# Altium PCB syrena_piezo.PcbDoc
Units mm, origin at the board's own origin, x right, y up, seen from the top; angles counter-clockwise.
Board outline 35.94 x 14.99 mm, 2 copper layers (Top Layer, Bottom Layer); 19 components, 15 nets, 54 pads, 10 vias.
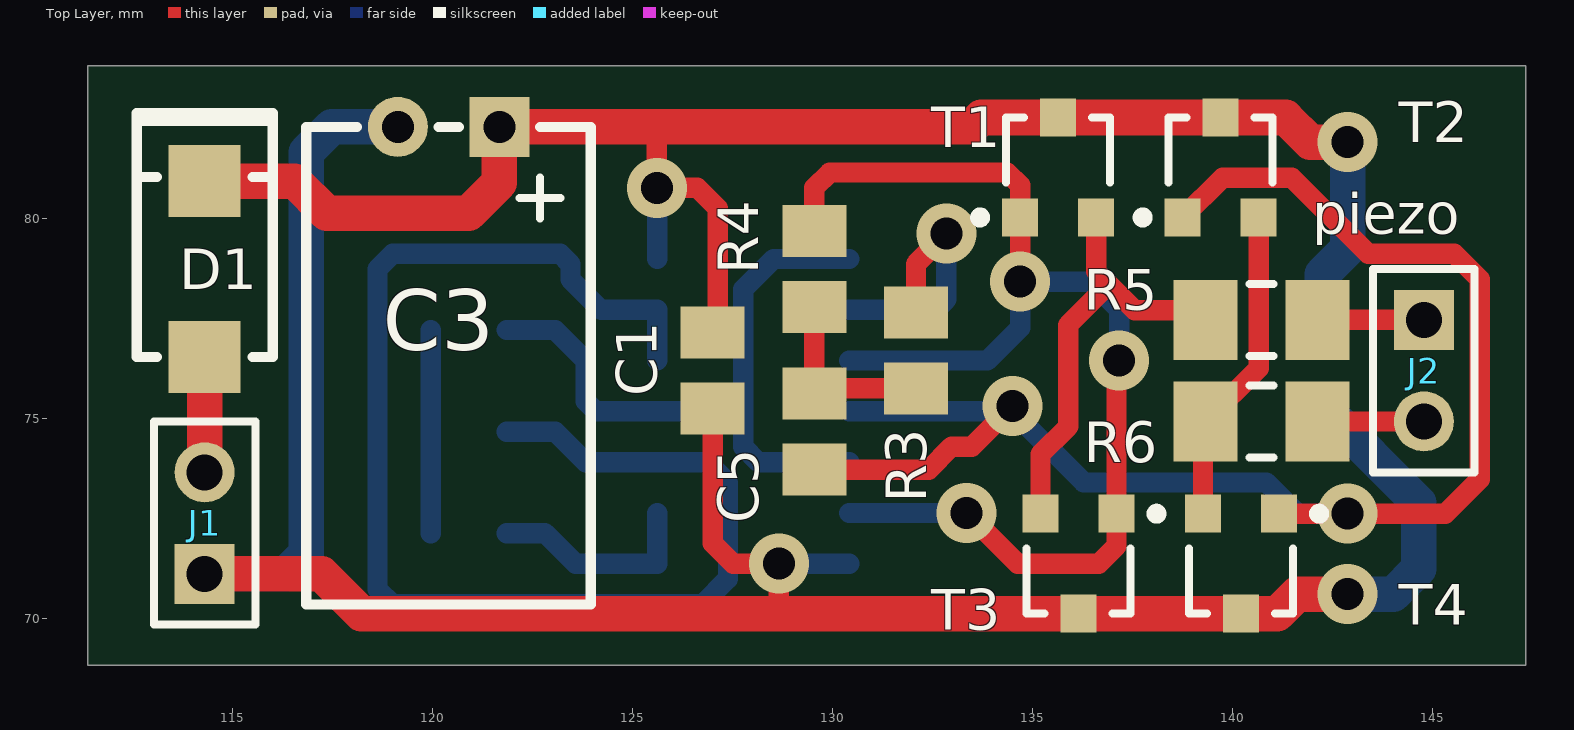
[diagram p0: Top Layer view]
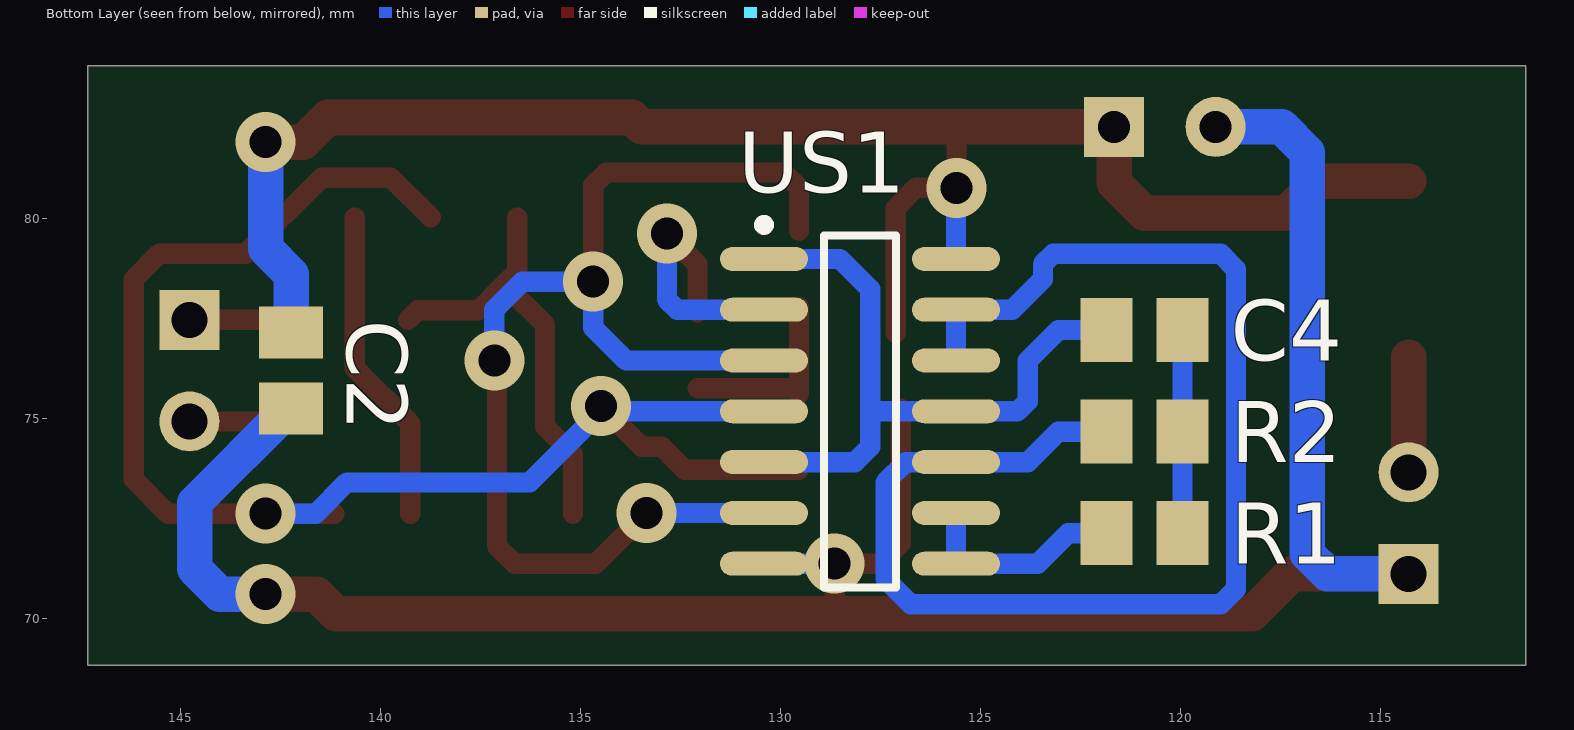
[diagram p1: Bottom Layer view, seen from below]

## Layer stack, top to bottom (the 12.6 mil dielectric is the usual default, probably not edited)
Top Layer: signal copper 0.0356
Dielectric: dielectric 0.32, FR-4, Dk 4.8
Bottom Layer: signal copper 0.0356

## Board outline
111.379,68.834 147.32,68.834 147.32,83.82 111.379,83.82

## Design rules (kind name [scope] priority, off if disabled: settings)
Clearance [All] p1: gap=0.254
PolygonConnect [All] p1: connectstyle=Relief reliefconductorwidth=0.254 reliefentries=4 polygonreliefangle="90 Angle"
RoomDefinition syrena_piezo [InComponentClass('syrena_piezo')] p1: confinementstyle=ConfineIn formatcopy=TRUE lockcomponents=FALSE outline 0,0 50.8,0 50.8,25.4 0,25.4
RoutingVias [All] p1: holewidth=0.711 width=1.27 viastyle="Through Hole" minholewidth=0.711 minwidth=1.27 maxholewidth=0.711 maxwidth=1.27
SilkscreenOverComponentPads [All] p1: minsilkscreentomaskgap=0.254
SolderMaskExpansion [All] p1: expansion=0.102
Width [All] p1: maxlimit=2.54 minlimit=0.254 preferedwidth=0.508
27 further rules are at their usual default settings.

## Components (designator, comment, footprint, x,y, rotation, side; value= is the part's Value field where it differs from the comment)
C1 "100n" MELF-0805 127,76.2 r90 top
C2 "1u" MELF-0805 142.24,76.2 r90 bottom
C3 "100u" "2,5/7mm le抗cy elektrolit" 120.396,82.296 r180 top
C4 "1u" MELF-0805 120.904,77.216 r0 bottom
C5 "100n" MELF-0805 129.54,74.676 r270 top
D1 "SS14" SMA/DO-214AC 114.3,78.74 r90 top
J1 "zasilanie" HDR1X2 114.3,71.12 r90 top
J2 "piezo" HDR1X2 144.78,77.47 r270 top
R1 "100k" MELF-0805 120.904,72.136 r0 bottom
R2 "180k" MELF-0805 120.904,74.676 r0 bottom
R3 "100k" MELF-0805 132.08,76.708 r90 top
R4 "1,8k" MELF-0805 129.54,78.74 r90 top
R5 "4,7" MELF-1206 140.716,77.47 r0 top
R6 "4,7" MELF-1206 140.716,74.93 r180 top
T1 "BC817-40" 318-08 135.636,81.28 r0 top
T2 "BC817-40" 318-08 139.7,81.28 r0 top
T3 "BC807-40" 318-08 136.144,71.374 r180 top
T4 "BC807-40" 318-08 140.208,71.374 r180 top
US1 "4011" 751A-03_N 128.016,75.184 r180 bottom

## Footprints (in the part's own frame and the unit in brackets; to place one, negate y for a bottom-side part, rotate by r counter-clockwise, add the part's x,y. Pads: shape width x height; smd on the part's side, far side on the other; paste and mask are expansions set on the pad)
"2,5/7mm le抗cy elektrolit" [mm]
  rect 1.5x1.5 hole 0.8: 1(-1.27,0)
  round 1.5 hole 0.8: 2(1.27,0)
  silkscreen extent -3.56,0 3.56,11.94
318-08 [mm] "SOT-23; 3 Leads; Body 3.0 x 2.6 mm, inc. leads (LxW max)"
  rect 0.9x0.95 smd: 1(-0.95,-1.25) 2(0.95,-1.25) 3(0,1.25)
  silkscreen extent -2.07,-1.37 1.3,1.25
751A-03_N [mm] "SOIC, 14-Leads, Body 8.7x3.9mm, Pitch 1.27mm, IPC Medium Density"
  oval 2.2x0.6 smd: 1(-2.4,3.81) 2(-2.4,2.54) 3(-2.4,1.27) 4(-2.4,0) 5(-2.4,-1.27) 6(-2.4,-2.54) 7(-2.4,-3.81) 8(2.4,-3.81) 9(2.4,-2.54) 10(2.4,-1.27) 11(2.4,0) 12(2.4,1.27) 13(2.4,2.54) 14(2.4,3.81)
  silkscreen extent -2.53,-4.4 0.9,4.78, body extent -2,-4.38 2,4.38, height 1.75
HDR1X2 [mm] "Connector; Header; 2 Position"
  rect 1.5x1.5 hole 0.9: 1(0,0)
  round 1.5 hole 0.9: 2(2.54,0)
  silkscreen extent -1.27,-1.27 3.81,1.27
MELF-0805 [mm] "Metal Electrode Face (MELF) Resistor; Body 2 x 1.4 mm (LxDia)"
  rect 1.3x1.6 smd: 1(-0.95,0) 2(0.95,0)
MELF-1206 [mm] "Metal Electrode Face (MELF) Resistor; Body 3.2 x 1.8 mm (LxDia)"
  rect 1.6x2 smd: 1(-1.4,0) 2(1.4,0)
  silkscreen extent -0.3,-0.9 0.3,0.9, body extent -2.3,-1.1 2.3,1.1, height 1.85
SMA/DO-214AC [mm]
  rect 1.8x1.8 smd: 1(-2.2,0) 2(2.2,0)
  silkscreen extent -2.2,-1.7 3.9,1.7

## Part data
C1 C2 C4 C5: library part kondensator
C3: library part "kond biegunowy", "Polarized Capacitor"
D1: library part "D Schottky", "Schottky Diode"
J1 J2: library part "Header 2", "Header, 2-Pin"
R1 R2 R3 R4 R5 R6: library part rezystor
T1 T2: library part BC846ALT1, "General Purpose Transistor NPN Silicon"
T3 T4: library part BC857ALT1, "General Purpose Transistor PNP Silicon"
US1: library part MC14011BD, "Quad 2-Input NAND Gate"

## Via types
v1: diameter 1.5, hole 0.8, Top Layer to Bottom Layer, 10 vias

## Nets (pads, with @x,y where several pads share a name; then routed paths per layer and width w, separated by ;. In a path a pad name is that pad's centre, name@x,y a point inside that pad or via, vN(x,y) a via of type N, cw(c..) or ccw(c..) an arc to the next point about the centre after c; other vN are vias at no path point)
GND: C1.1 C2.1 C3.2 J1.1 T3.3 T4.3 US1.7 | length 60.3
  Top Layer w0.508: C1.1 127,71.882 127.508,71.374 v1(128.651,71.374) 128.651,70.124
  Top Layer w0.889: J1.1 117.221,71.12 118.217,70.124 128.651,70.124 T3.3 T4.3 141.117,70.124 141.605,70.612 v1(142.875,70.612)
  Bottom Layer w0.508: v1@128.397,71.755 128.651,71.755 129.032,71.374 US1.7
  Bottom Layer w0.889: J1.1 116.332,71.12 116.84,71.628 116.84,81.661 117.475,82.296 C3.2 ; C2.1 142.297,75.25 144.653,72.894 144.653,71.247 144.018,70.612 v1(142.875,70.612)
NetC4_1: C4.1 R1.1 R2.1 | length 5.1
  Bottom Layer w0.508: R1.1 R2.1 C4.1
NetC4_2: C4.2 US1.1 US1.5 US1.11 | length 17.1
  Bottom Layer w0.508: C4.2 123.063,77.216 123.825,76.454 123.825,75.438 124.079,75.184 US1.11 127.762,75.184 ; US1.5 128.143,73.914 127.762,74.295 127.762,75.184 ; US1.1 128.524,78.994 127.762,78.232 127.762,77.724 127.762,75.184
NetC5_1: C5.1 R3.1 R4.1 | length 4.6
  Top Layer w0.508: C5.1 R4.1 ; C5.1@129.672,75.758 R3.1
NetC5_2: C5.2 T2.1 T4.1 US1.4 | length 38.4
  Top Layer w0.508: C5.2 132.4,73.726 132.969,74.295 133.477,74.295 v1(134.493,75.311) ; T2.1 139.746,81.026 141.478,81.026 143.383,79.121 145.542,79.121 146.177,78.486 146.177,73.482 145.319,72.624 143.49,72.624 T4.1
  Bottom Layer w0.508: US1.4 134.493,75.184 136.271,73.406 140.843,73.406 141.625,72.624 v1(142.875,72.624)
NetD1_1: D1.1 J1.2 | length 2.9
  Top Layer w0.889: J1.2 D1.1
NetJ2_1: J2.1 R5.2 | length 2.7
  Top Layer w0.508: R5.2 J2.1
NetJ2_2: J2.2 R6.1 | length 2.7
  Top Layer w0.508: R6.1 J2.2
NetR1_2: R1.2 US1.8 US1.9 | length 5.3
  Bottom Layer w0.508: R1.2 122.809,72.136 123.571,71.374 US1.8 US1.9
NetR2_2: R2.2 US1.10 US1.12 US1.13 | length 34.9
  Bottom Layer w0.508: R2.2 123.063,74.676 123.825,73.914 US1.10 126.873,73.914 127.381,73.406 127.381,70.993 126.746,70.358 118.999,70.358 118.618,70.739 118.618,78.74 118.999,79.121 123.19,79.121 123.444,78.867 123.444,78.486 124.206,77.724 US1.13 US1.12
NetR3_2: R3.2 US1.2 | length 6.5
  Top Layer w0.508: R3.2 132.08,78.867 v1(132.842,79.629)
  Bottom Layer w0.508: US1.2 132.588,77.724 132.842,77.978 v1(132.842,79.629)
NetR4_2: R4.2 T1.1 T3.1 US1.3 US1.6 | length 30.5
  Top Layer w0.508: R4.2 129.54,80.772 129.921,81.153 134.366,81.153 134.686,80.833 T1.1 v1(134.686,78.425) ; v1(133.35,72.644) 134.62,71.374 136.652,71.374 137.094,71.816 T3.1 v1@137.094,76.2
  Bottom Layer w0.508: US1.6 v1(133.35,72.644) ; US1.3 133.863,76.454 134.686,77.277 v1(134.686,78.425) 136.459,78.425 137.16,77.724 v1(137.16,76.454)
NetR5_1: R5.1 T1.2 T3.2 | length 11
  Top Layer w0.508: T3.2 135.194,74.107 135.89,74.803 135.89,77.343 136.906,78.359 ; 136.586,78.679 136.906,78.359 ; 136.586,78.74 T1.2 ; R5.1 139.074,77.712 137.553,77.712 136.906,78.359
NetR6_2: R6.2 T2.2 T4.2 | length 8
  Top Layer w0.508: T4.2 139.258,74.872 R6.2 140.65,76.264 T2.2
VDD: C1.2 C2.2 C3.1 D1.2 T1.3 T2.3 US1.14 | length 44.1
  Top Layer w0.508: 125.603,82.296 v1(125.603,80.772) 126.619,80.772 127.127,80.264 C1.2@127.127,77.15
  Top Layer w0.889: D1.2 116.545,80.94 117.348,80.137 120.904,80.137 121.666,80.899 C3.1 125.603,82.296 133.477,82.296 133.711,82.53 T1.3 T2.3 141.321,82.53 141.936,81.915 v1(142.875,81.915)
  Bottom Layer w0.508: US1.14 v1@125.616,80.759
  Bottom Layer w0.889: C2.2 142.24,78.613 142.875,79.248 v1(142.875,81.915)

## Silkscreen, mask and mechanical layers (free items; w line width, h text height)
Mechanical 1:
  the board outline again, w0.254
